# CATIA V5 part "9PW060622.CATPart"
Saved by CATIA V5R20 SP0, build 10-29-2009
Part number: 9PW060622
Revision: ANY
Definition: UNKNOWN
Nomenclature: 9PW060622
Source: Unknown
Bounding box of the stored display mesh (mm): x -124.5 to 0, y -9.384 to 3, z -3.1 to 3.1
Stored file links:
  C:\Users\Utente\Desktop\IO LAVORO\3D X SITO CF\CUMSA\3D files PW\pw060622\pw060622_ejection\9PW060622.CATPart
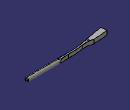
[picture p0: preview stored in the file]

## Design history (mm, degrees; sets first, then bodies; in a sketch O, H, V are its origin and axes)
Body1 "Chaflán1" (main body)
  Solid1: solid without history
